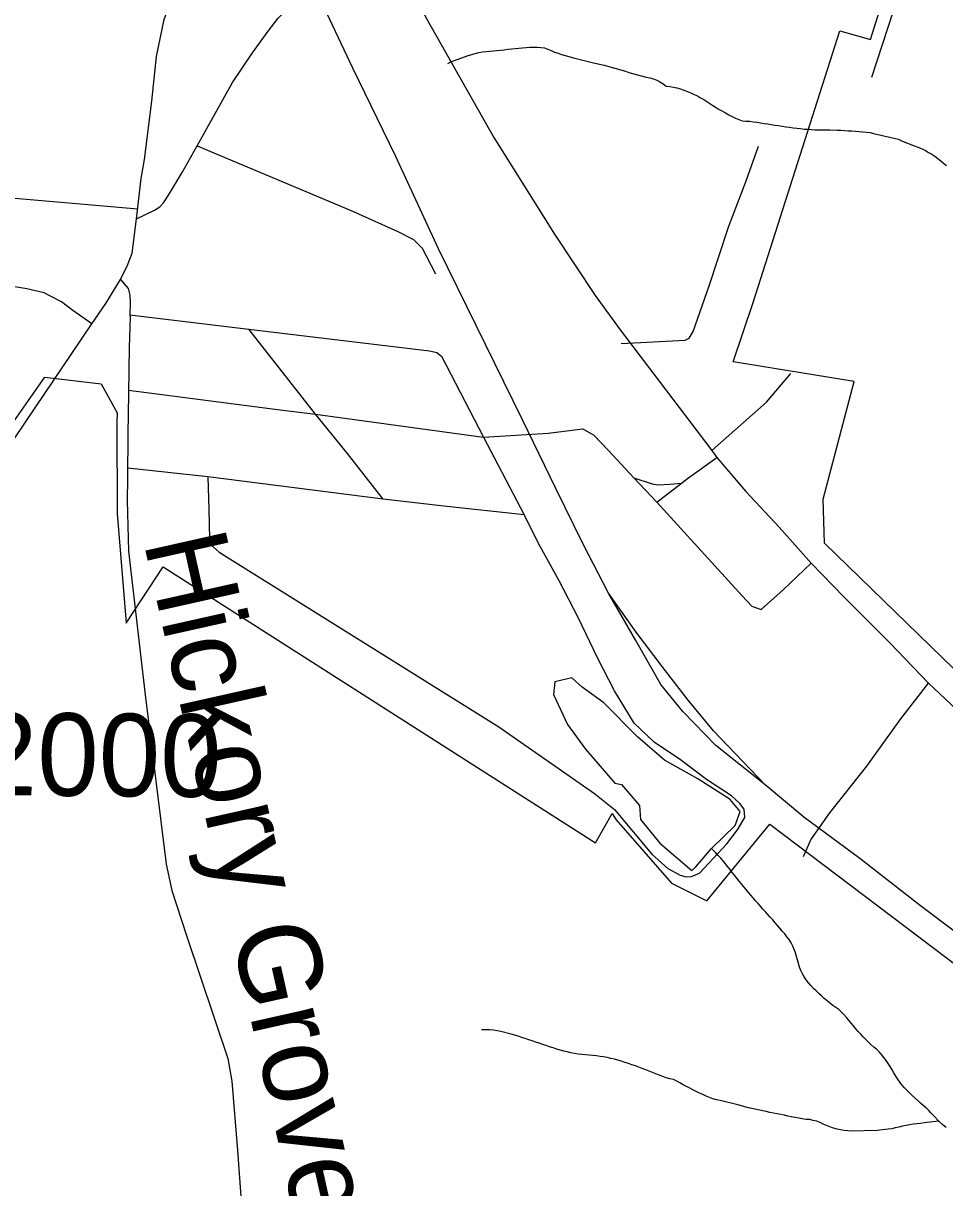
# Model space of a CAD drawing. Extents: x 1379453 to 1387082, y 594364 to 596664.
# Drawn here: x 1380139.8 to 1380304.5, y 595868.7 to 596077 of the extents above; entities that cross this region are included whole.
import ezdxf

# ---------------------------------------------------------------- set-up
doc = ezdxf.new("R2010")
doc.units = 0
for name, color, linetype in [('Old_Level_11', 7, 'Continuous'), ('Old_Level_29', 7, 'Continuous'), ('Old_Level_32', 7, 'Continuous'), ('Old_Level_35', 7, 'Continuous'), ('Old_Level_44', 7, 'Continuous'), ('Old_Level_48', 7, 'Continuous'), ('Old_Level_49', 7, 'Continuous'), ('Old_Level_59', 7, 'Continuous'), ('Old_Level_62', 7, 'Continuous'), ('Old_Level_8', 7, 'Continuous')]:
    doc.layers.add(name, color=color, linetype=linetype)

msp = doc.modelspace()

# ---------------------------------------------------------------- linework, layer by layer
at = {"layer": 'Old_Level_29'}
for points in [[(1380160.02, 596042.03), (1380160.83, 596049.23), (1380161.44, 596052.59), (1380162.72, 596063.05), (1380163.55, 596071.03), (1380164.94, 596077.63), (1380167.52, 596084.82), (1380170.44, 596091.69), (1380170.78, 596092.66), (1380172.95, 596098.94), (1380174.87, 596103.36), (1380175.61, 596105.57), (1380176, 596106.91), (1380176.05, 596107.79), (1380176.21, 596109.13), (1380175.94, 596110.29), (1380170.86, 596120.61), (1380166.84, 596128.69), (1380166.18, 596130.03), (1380160.98, 596141.31), (1380156.51, 596150.17), (1380151.21, 596160.9), (1380142.92, 596177.94)], [(1380204.53, 596092.33), (1380206.39, 596089.06), (1380211.66, 596078.14), (1380223.88, 596056.55), (1380234.7, 596039.29), (1380241.97, 596028.31), (1380246.45, 596022.15), (1380262.87, 596000.58), (1380263.77, 595999.32), (1380268.91, 595993.22), (1380274.88, 595986.84), (1380280.62, 595980.44), (1380286.53, 595974.34), (1380294.69, 595966.17), (1380301.61, 595958.93), (1380328.88, 595933.24), (1380339.13, 595925.25), (1380353.32, 595914.75), (1380366.47, 595904.76), (1380375.33, 595898.26), (1380418.73, 595865.44)], [(1380157.16, 596031.16), (1380158.37, 596033.74), (1380159.2, 596035.85), (1380160.02, 596042.03)], [(1380151.99, 596023.25), (1380154.5, 596026.88), (1380157.16, 596031.16)], [(1380133.35, 595995.65), (1380140.36, 596006), (1380146.68, 596015.34), (1380151.99, 596023.25)]]:
    msp.add_lwpolyline(points, dxfattribs=at)
at = {"layer": 'Old_Level_32'}
for points in [[(1380304.16, 596106.46), (1380297.25, 596085.24), (1380291.39, 596067.26)], [(1380160.02, 596042.03), (1380163.22, 596043.56), (1380164.18, 596044.15), (1380164.8, 596044.84), (1380165.72, 596046.22), (1380168.14, 596050.27), (1380170.85, 596055.06), (1380177.14, 596066.38), (1380180.71, 596071.72), (1380183.51, 596075.58), (1380185.3, 596077.91), (1380189.19, 596081.92), (1380191.65, 596083.54)], [(1380151.99, 596023.25), (1380148.64, 596025.59), (1380146.58, 596027.18), (1380144.4, 596028.31), (1380143.5, 596028.77), (1380140.41, 596029.47), (1380133.55, 596030.59)], [(1380157.16, 596031.16), (1380158.52, 596029.53), (1380158.8, 596028.33), (1380158.88, 596026.97), (1380158.8, 596024.81), (1380158.86, 596024.41), (1380158.7, 596019.05), (1380158.54, 596010.79), (1380158.44, 596003.52), (1380158.41, 595995.63), (1380158.33, 595991.61), (1380158.59, 595982.55), (1380161.52, 595956.85), (1380165.28, 595926.57), (1380166.29, 595921.88), (1380168.92, 595913.8), (1380176.31, 595891.85), (1380177.05, 595887.78), (1380178.06, 595875.39), (1380178.87, 595863.87), (1380179.27, 595857.22), (1380180.97, 595850.35)]]:
    msp.add_lwpolyline(points, dxfattribs=at)
at = {"layer": 'Old_Level_35'}
for p, q in [((1380158.8, 596024.81), (1380180.09, 596022.27)), ((1380191.97, 596007.04), (1380180.09, 596022.27)), ((1380191.97, 596007.04), (1380222.03, 596002.95)), ((1380222.03, 596002.95), (1380229.31, 595989.06)), ((1380172.75, 595995.86), (1380158.42, 595997.39)), ((1380204.09, 595991.87), (1380172.75, 595995.86)), ((1380248.93, 595995.67), (1380253, 595991.33)), ((1380253, 595991.33), (1380257.41, 595994.74))]:
    msp.add_line(p, q, dxfattribs=at)
for points in [[(1380170.85, 596055.06), (1380198.48, 596043.43), (1380206.7, 596039.75), (1380209.53, 596038.3), (1380211.09, 596036.74), (1380213.44, 596032.19)], [(1380246.61, 596019.69), (1380258.09, 596020.31), (1380258.82, 596020.69), (1380259.49, 596021.87), (1380262.37, 596030.04), (1380265.88, 596040.67), (1380269, 596048.82), (1380271.18, 596055)], [(1380107.64, 596050.08), (1380135.42, 596045.93), (1380160.22, 596043.78)], [(1380180.09, 596022.27), (1380212.39, 596018.37), (1380213.66, 596018.09), (1380214.53, 596017.43), (1380222.03, 596002.95)], [(1380262.87, 596000.58), (1380272.62, 596009.2), (1380276.95, 596014.34)], [(1380158.55, 596011.35), (1380185.67, 596007.86), (1380191.97, 596007.04)], [(1380204.09, 595991.87), (1380197.69, 596000.06), (1380191.97, 596007.04)], [(1380222.03, 596002.95), (1380233.58, 596003.66), (1380239.77, 596004.44), (1380241.74, 596003.34), (1380244.38, 596000.54), (1380248.93, 595995.67)], [(1380257.41, 595994.74), (1380258.49, 595995.57), (1380263.77, 595999.32)], [(1380172.75, 595995.86), (1380172.9, 595990.08), (1380173.04, 595984.78), (1380173.17, 595983.79), (1380174.76, 595982.4), (1380224.76, 595951.16), (1380241.87, 595939.22), (1380245.47, 595936.38), (1380252.12, 595928.35), (1380255.01, 595925.78), (1380257.21, 595924.59), (1380258.25, 595924.32), (1380259.21, 595924.38), (1380260.67, 595924.98), (1380265.55, 595930.2), (1380267.46, 595932.71), (1380268.76, 595934.94), (1380268.64, 595936.43), (1380267.85, 595937.44), (1380266.36, 595938.82), (1380261.88, 595941.75), (1380257.26, 595945.25), (1380252.55, 595948.43), (1380248.96, 595951.81), (1380245.45, 595957.6), (1380242.49, 595963.37), (1380238.95, 595970.68), (1380235.53, 595977.26), (1380232.12, 595983.52), (1380229.31, 595989.06)], [(1380248.93, 595995.67), (1380252.19, 595994.61), (1380253.24, 595994.42), (1380255.34, 595994.54), (1380257.41, 595994.74)], [(1380229.31, 595989.06), (1380214.95, 595990.6), (1380204.09, 595991.87)], [(1380253, 595991.33), (1380268.28, 595974.55), (1380269.99, 595972.73), (1380271.65, 595972.13), (1380275.6, 595975.62), (1380280.62, 595980.44)], [(1380279.25, 595927.96), (1380280.54, 595930.96), (1380283.96, 595935.74), (1380290.53, 595944.12), (1380296.62, 595952.59), (1380301.61, 595958.93)]]:
    msp.add_lwpolyline(points, dxfattribs=at)
at = {"layer": 'Old_Level_44'}
for points in [[(1380312.9, 595909.53), (1380300.13, 595919.1), (1380289.32, 595927.58), (1380279.3, 595935), (1380272.41, 595940.8), (1380263.17, 595950.44), (1380258.61, 595955.93), (1380253.98, 595961.92), (1380249.35, 595968.05), (1380244.35, 595975.08), (1380239.89, 595983.7), (1380234.97, 595993.77), (1380229, 596006.04), (1380220.69, 596022.93), (1380213.97, 596036.66), (1380206.29, 596053.29), (1380198.66, 596068.96), (1380192.47, 596082.12), (1380185.52, 596096.08), (1380177.44, 596112.65), (1380169.29, 596129.78), (1380163.55, 596141.56)], [(1380312.9, 595909.53), (1380300.13, 595919.1), (1380289.32, 595927.58), (1380279.3, 595935), (1380272.41, 595940.8), (1380263.57, 595947.8), (1380257.65, 595953.89), (1380253.72, 595958.72), (1380249.29, 595966.6), (1380244.35, 595975.08), (1380239.89, 595983.7), (1380234.97, 595993.77), (1380229, 596006.04), (1380220.69, 596022.93), (1380213.97, 596036.66), (1380206.29, 596053.29), (1380198.66, 596068.96), (1380192.47, 596082.12)]]:
    msp.add_lwpolyline(points, dxfattribs=at)
at = {"layer": 'Old_Level_48'}
for points in [[(1380306.1, 595961.49), (1380283.01, 595983.98), (1380282.74, 595991.87), (1380288.32, 596012.89), (1380266.64, 596016.44), (1380270.23, 596027.03), (1380285.74, 596075.63), (1380291.22, 596074.09), (1380294.95, 596086.05), (1380302.91, 596083.24), (1380314.44, 596118.5), (1380286.73, 596124.3), (1380274.6, 596118.89), (1380271.54, 596124.6), (1380193.74, 596271.38), (1380220.87, 596276.59), (1380219.29, 596281.97), (1380217.17, 596306.95), (1380216.79, 596311.89), (1380184.45, 596305.78), (1380172.72, 596328.84)], [(1380137.37, 596004.74), (1380143.62, 596013.67), (1380153.67, 596012.52), (1380156.52, 596007.3), (1380156.5, 596005.56), (1380156.53, 595989.28)], [(1380156.53, 595989.28), (1380158.15, 595969.68), (1380164.77, 595979.74), (1380242.07, 595930.38), (1380245.01, 595935.66), (1380245.74, 595934.5), (1380255.64, 595923.18), (1380261.94, 595920.05), (1380273.23, 595933.73), (1380333.58, 595888.08)]]:
    msp.add_lwpolyline(points, dxfattribs=at)
at = {"layer": 'Old_Level_49'}
for points in [[(1380306.1, 595961.49), (1380283.01, 595983.98), (1380282.74, 595991.87), (1380288.32, 596012.89), (1380266.64, 596016.44), (1380270.23, 596027.03), (1380285.74, 596075.63), (1380291.22, 596074.09), (1380294.95, 596086.05), (1380302.91, 596083.24), (1380314.44, 596118.5), (1380286.73, 596124.3), (1380274.6, 596118.89), (1380271.54, 596124.6), (1380193.74, 596271.38), (1380220.87, 596276.59), (1380219.29, 596281.97), (1380217.17, 596306.95), (1380216.79, 596311.89), (1380184.45, 596305.78), (1380172.72, 596328.84)], [(1380137.37, 596004.74), (1380143.62, 596013.67), (1380153.67, 596012.52), (1380156.52, 596007.3), (1380156.5, 596005.56), (1380156.53, 595989.28)], [(1380156.53, 595989.28), (1380158.15, 595969.68), (1380164.77, 595979.74), (1380242.07, 595930.38), (1380245.01, 595935.66), (1380245.74, 595934.5), (1380255.64, 595923.18), (1380261.94, 595920.05), (1380273.23, 595933.73), (1380333.58, 595888.08)]]:
    msp.add_lwpolyline(points, dxfattribs=at)
at = {"layer": 'Old_Level_59'}
for points in [[(1380215.66, 596069.77), (1380216.21, 596070.11), (1380219.3, 596071.19), (1380219.93, 596071.39), (1380220.56, 596071.59), (1380221.19, 596071.75), (1380221.83, 596071.87), (1380222.49, 596071.92), (1380225.73, 596072.25), (1380226.38, 596072.34), (1380227.03, 596072.42), (1380227.69, 596072.49), (1380228.34, 596072.56), (1380228.99, 596072.62), (1380229.65, 596072.67), (1380230.3, 596072.69), (1380230.97, 596072.7), (1380231.63, 596072.71), (1380232.28, 596072.67), (1380232.93, 596072.58), (1380233.54, 596072.38), (1380234.14, 596072.11), (1380234.74, 596071.83), (1380235.37, 596071.62), (1380236, 596071.42), (1380236.63, 596071.23), (1380237.26, 596071.06), (1380237.89, 596070.89), (1380241.69, 596069.9), (1380243.62, 596069.5), (1380244.25, 596069.34), (1380244.88, 596069.16), (1380245.51, 596068.98), (1380246.14, 596068.79), (1380246.77, 596068.59), (1380247.4, 596068.4), (1380248.03, 596068.19), (1380251.12, 596067.36), (1380251.77, 596067.24), (1380252.39, 596067.05), (1380252.99, 596066.8), (1380253.58, 596066.49), (1380254.15, 596066.16), (1380254.67, 596065.76), (1380255.31, 596065.65), (1380255.97, 596065.58), (1380256.61, 596065.45), (1380257.24, 596065.25), (1380257.85, 596065.03), (1380258.47, 596064.79), (1380259.07, 596064.54), (1380259.67, 596064.27), (1380260.27, 596063.98), (1380260.84, 596063.67), (1380261.41, 596063.35), (1380261.98, 596063.01), (1380262.5, 596062.62), (1380263.04, 596062.25), (1380263.61, 596061.92), (1380264.18, 596061.59), (1380264.75, 596061.27), (1380265.32, 596060.95), (1380265.9, 596060.63), (1380266.47, 596060.32), (1380267.06, 596060.02), (1380267.65, 596059.75), (1380268.28, 596059.54), (1380268.93, 596059.5), (1380269.59, 596059.45), (1380270.24, 596059.36), (1380270.89, 596059.27), (1380271.54, 596059.17), (1380272.18, 596059.08), (1380272.83, 596058.98), (1380273.48, 596058.88), (1380274.13, 596058.78), (1380274.78, 596058.68), (1380275.43, 596058.58), (1380276.08, 596058.49), (1380276.73, 596058.4), (1380277.38, 596058.3), (1380278.03, 596058.22), (1380278.68, 596058.14), (1380279.34, 596058.07), (1380279.99, 596058.02), (1380280.65, 596057.98), (1380281.3, 596057.95), (1380281.96, 596057.95), (1380282.62, 596057.95), (1380283.27, 596057.95), (1380283.93, 596057.94), (1380285.24, 596057.87), (1380285.89, 596057.84), (1380286.55, 596057.81), (1380287.2, 596057.77), (1380287.86, 596057.73), (1380288.52, 596057.69), (1380289.17, 596057.64), (1380289.83, 596057.58), (1380290.48, 596057.52)], [(1380290.48, 596057.52), (1380291.13, 596057.44), (1380291.77, 596057.29), (1380296.19, 596056.23), (1380296.78, 596055.95), (1380299.22, 596054.98), (1380299.84, 596054.78), (1380300.44, 596054.5), (1380301.02, 596054.21), (1380301.61, 596053.89), (1380302.17, 596053.55), (1380302.71, 596053.19), (1380303.24, 596052.8), (1380303.76, 596052.4), (1380304.27, 596051.98), (1380304.77, 596051.55)]]:
    msp.add_lwpolyline(points, dxfattribs=at)
at = {"layer": 'Old_Level_62'}
for points in [[(1380262.81, 595929.39), (1380266.99, 595933.48), (1380267.93, 595936.02), (1380266.1, 595938.12), (1380260.35, 595941.87), (1380254.36, 595945.16), (1380249.53, 595949.37), (1380243.57, 595955.44), (1380239.66, 595958.25), (1380237.83, 595959.88), (1380234.81, 595959.22), (1380234.56, 595956.9), (1380237.06, 595951.56), (1380240.27, 595947.13), (1380245.53, 595941.07), (1380246.69, 595940.83), (1380249.9, 595937.1), (1380250.11, 595934.55), (1380253.54, 595930.35), (1380259.28, 595925.44), (1380259.99, 595926.13), (1380262.81, 595929.39)], [(1380303.42, 595880.63), (1380302.52, 595881.59), (1380302.07, 595882.07), (1380301.62, 595882.54), (1380301.14, 595883), (1380300.64, 595883.42), (1380300.14, 595883.85), (1380299.66, 595884.29), (1380298.69, 595885.19), (1380298.22, 595885.64), (1380297.75, 595886.11), (1380297.31, 595886.59), (1380296.88, 595887.08), (1380296.48, 595887.6), (1380296.11, 595888.14), (1380295.75, 595888.69), (1380295.4, 595889.25), (1380295.06, 595889.81), (1380294.71, 595890.37), (1380294.36, 595890.92), (1380294, 595891.47), (1380293.61, 595892), (1380293.19, 595892.51), (1380292.75, 595893), (1380292.31, 595893.48), (1380291.78, 595893.85), (1380291.29, 595894.3), (1380290.83, 595894.76), (1380290.37, 595895.23), (1380289.91, 595895.7), (1380289.46, 595896.18), (1380289.01, 595896.66), (1380288.57, 595897.15), (1380288.15, 595897.64), (1380287.74, 595898.16), (1380287.35, 595898.69), (1380286.92, 595899.18), (1380286.47, 595899.67), (1380286.01, 595900.14), (1380285.53, 595900.58), (1380285, 595900.96), (1380284.45, 595901.33), (1380283.94, 595901.74), (1380283.44, 595902.16), (1380282.93, 595902.58), (1380282.43, 595903.01), (1380281.95, 595903.45), (1380281.47, 595903.9), (1380281.01, 595904.37), (1380280.57, 595904.86), (1380280.14, 595905.35), (1380279.73, 595905.87), (1380279.37, 595906.41), (1380279.03, 595906.98), (1380278.74, 595907.57), (1380278.52, 595908.18), (1380278.33, 595908.81), (1380278.15, 595909.45), (1380277.98, 595910.08), (1380277.79, 595910.71), (1380277.58, 595911.33), (1380277.33, 595911.94), (1380277.04, 595912.54), (1380276.69, 595913.09), (1380276.28, 595913.6), (1380275.87, 595914.11), (1380275.44, 595914.61), (1380275.02, 595915.11), (1380274.59, 595915.61), (1380274.16, 595916.1), (1380273.73, 595916.6), (1380273.29, 595917.09), (1380272.85, 595917.58), (1380272.42, 595918.07), (1380271.98, 595918.56), (1380271.55, 595919.05), (1380271.11, 595919.55), (1380270.68, 595920.04), (1380270.25, 595920.54), (1380269.82, 595921.03), (1380269.4, 595921.54), (1380268.98, 595922.04), (1380268.57, 595922.55), (1380268.15, 595923.06), (1380267.74, 595923.57), (1380267.33, 595924.09), (1380266.92, 595924.6), (1380266.51, 595925.11), (1380266.1, 595925.62), (1380265.69, 595926.13), (1380265.27, 595926.64), (1380264.85, 595927.15), (1380264.44, 595927.65), (1380264, 595928.14), (1380263.55, 595928.62), (1380262.81, 595929.39)], [(1380227.63, 595896), (1380227, 595896.2), (1380225.11, 595896.67), (1380223.83, 595896.89), (1380223.18, 595896.93), (1380222.52, 595896.95), (1380221.7, 595896.97)], [(1380303.42, 595880.63), (1380300.81, 595880.31), (1380300.16, 595880.22), (1380299.51, 595880.14), (1380298.86, 595880.05), (1380298.21, 595879.95), (1380297.56, 595879.84), (1380296.92, 595879.71), (1380296.28, 595879.56), (1380295.64, 595879.4), (1380295, 595879.27), (1380294.35, 595879.18), (1380292.42, 595878.96), (1380287.82, 595878.82), (1380287.17, 595878.86), (1380286.52, 595878.95), (1380285.87, 595879.06), (1380285.23, 595879.21), (1380284.59, 595879.38), (1380283.97, 595879.59), (1380283.35, 595879.82), (1380282.75, 595880.07), (1380282.22, 595880.4), (1380281.59, 595880.59), (1380280.95, 595880.75), (1380280.31, 595880.9), (1380279.67, 595880.9), (1380279.02, 595881.02), (1380278.38, 595881.15), (1380277.74, 595881.27), (1380277.09, 595881.4), (1380276.45, 595881.53), (1380275.81, 595881.66), (1380275.16, 595881.79), (1380274.52, 595881.92), (1380273.87, 595882.05), (1380273.23, 595882.18), (1380272.59, 595882.32), (1380269.4, 595882.98), (1380268.77, 595883.15), (1380268.14, 595883.33), (1380267.51, 595883.52), (1380264.32, 595884.31), (1380263.67, 595884.43), (1380263.04, 595884.6), (1380262.43, 595884.83), (1380261.83, 595885.09), (1380261.23, 595885.36), (1380260.64, 595885.65), (1380260.05, 595885.94), (1380258.29, 595886.83), (1380257.71, 595887.14), (1380257.14, 595887.47), (1380256.57, 595887.79), (1380255.97, 595888.04), (1380255.33, 595888.2), (1380254.69, 595888.37), (1380254.07, 595888.58), (1380253.46, 595888.82), (1380252.85, 595889.06), (1380252.24, 595889.31), (1380251.63, 595889.56), (1380251.03, 595889.81), (1380250.42, 595890.06), (1380249.8, 595890.29), (1380249.19, 595890.51), (1380248.57, 595890.72), (1380247.94, 595890.93), (1380247.32, 595891.13), (1380246.69, 595891.33), (1380246.05, 595891.51), (1380245.42, 595891.68), (1380244.79, 595891.85), (1380244.14, 595891.99), (1380243.5, 595892.11), (1380242.86, 595892.21), (1380242.21, 595892.29), (1380241.55, 595892.35), (1380240.9, 595892.42), (1380240.24, 595892.47), (1380239.58, 595892.54), (1380238.93, 595892.62), (1380238.28, 595892.72), (1380237.65, 595892.84), (1380237, 595892.99), (1380236.37, 595893.15), (1380235.73, 595893.33), (1380235.11, 595893.52), (1380234.48, 595893.72), (1380233.85, 595893.92), (1380233.23, 595894.13), (1380232.61, 595894.33), (1380231.98, 595894.55), (1380231.37, 595894.76), (1380230.74, 595894.97), (1380230.11, 595895.18), (1380229.5, 595895.39), (1380228.87, 595895.6), (1380228.25, 595895.8), (1380227.63, 595896)], [(1380304.72, 595879.48), (1380304.19, 595879.88), (1380303.42, 595880.63)]]:
    msp.add_lwpolyline(points, dxfattribs=at)

# ---------------------------------------------------------------- texts
at = {"layer": 'Old_Level_11'}
msp.add_text('Hickory Grove Rd.', height=14.7638, rotation=282.6416, dxfattribs=at).set_placement((1380161.23, 595984.25))
at = {"layer": 'Old_Level_8'}
msp.add_text('2000', height=14.764, rotation=359.52, dxfattribs=at).set_placement((1380131.23, 595938.95))

doc.saveas('drawing.dxf')
